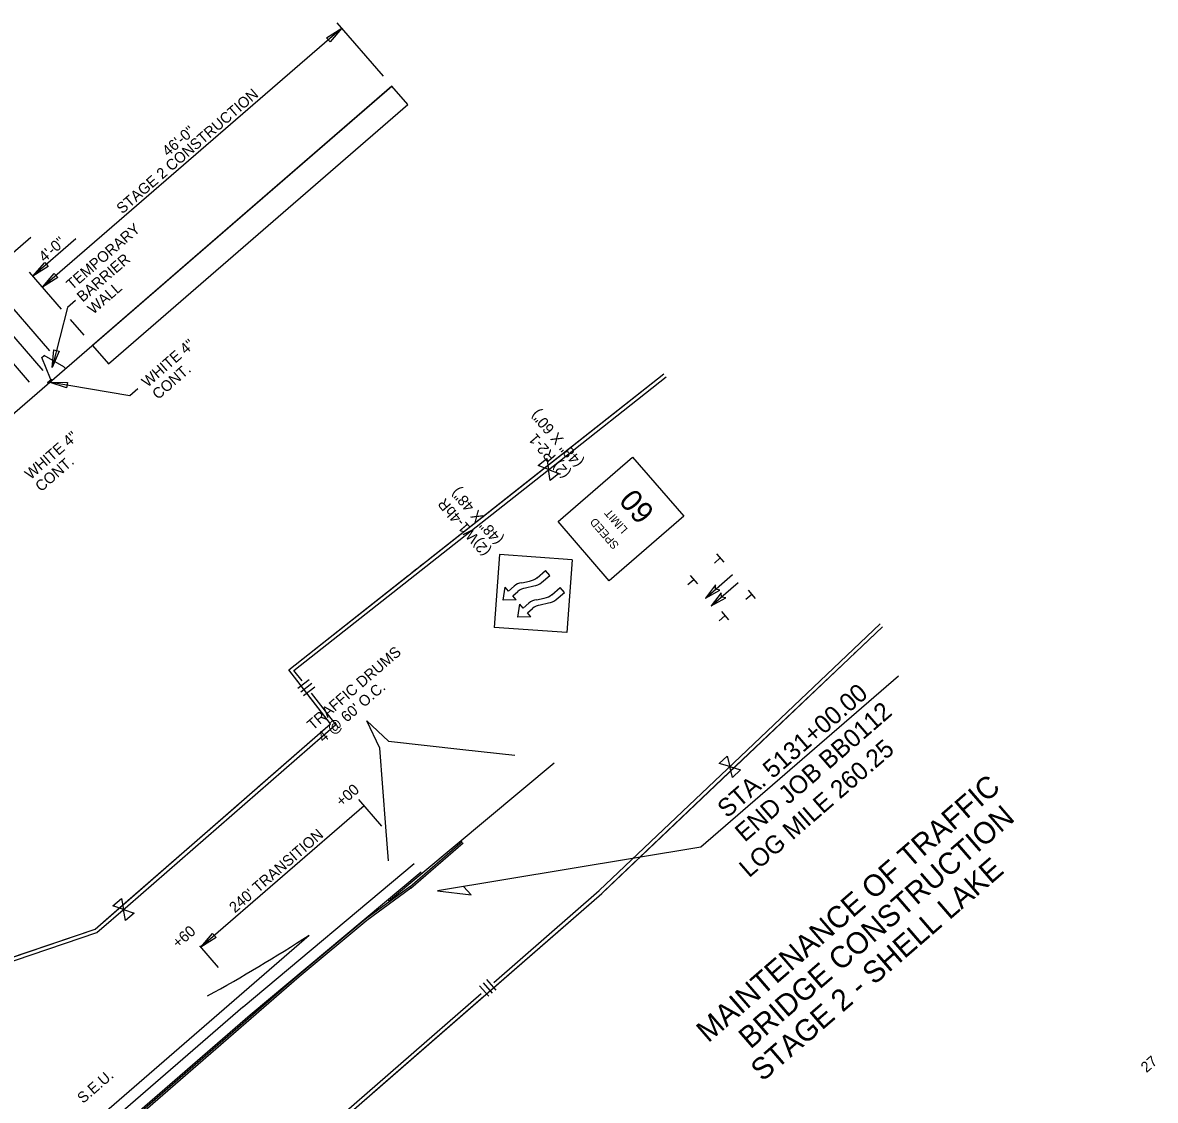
# Model space of a CAD drawing. Extents: x 259983 to 267998, y 211467 to 219827.
# Drawn here: x 263992 to 265251, y 216417 to 217614 of the extents above; entities that cross this region are included whole.
import ezdxf

# ---------------------------------------------------------------- set-up
doc = ezdxf.new("R2010")
doc.units = 0
for name, color, linetype in [('1', 7, 'Continuous'), ('Default', 7, 'Continuous'), ('Level 24', 7, 'Continuous'), ('Level 43', 7, 'Continuous'), ('Level 58', 7, 'Continuous'), ('Level 59', 7, 'Continuous'), ('Level 6', 7, 'Continuous'), ('R-W - CofA', 7, 'Continuous'), ('R_Border Notes', 7, 'Continuous'), ('R_MOT', 7, 'Continuous'), ('R_MOT STAGE 1', 7, 'Continuous'), ('R_MOT STAGE 2', 7, 'Continuous')]:
    doc.layers.add(name, color=color, linetype=linetype)

msp = doc.modelspace()

# ---------------------------------------------------------------- linework, layer by layer
at = {"layer": '1'}
for p, q in [((264346.9, 217608.3), (264014.1, 217320.3)), ((264393, 217554.9), (264341.6, 217614.3)), ((264420.4, 217523.3), (264402.6, 217543.9)), ((264001.1, 217375.6), (263951, 217332.2)), ((264051.4, 217373.9), (264003.6, 217332.5)), ((264022.4, 217249.7), (263946.2, 217337.7)), ((264035.3, 217295.9), (263999.7, 217337)), ((263999.9, 217214.6), (263924.5, 217301.7)), ((264015, 217227.7), (263961.8, 217289.1)), ((264060.4, 217267), (264045.3, 217284.4)), ((264111.1, 217199.5), (264021.7, 217214.7)), ((264120, 217207.2), (264111.1, 217199.5))]:
    msp.add_line(p, q, dxfattribs=at)
for points in [[(264329.9, 217597.6), (264346.9, 217608.3), (264333.8, 217593.1)], [(264020.5, 217343.2), (264003.6, 217332.5), (264016.6, 217347.8)], [(264031.1, 217331), (264014.1, 217320.3), (264027.1, 217335.6)], [(264032.7, 217249.3), (264024.9, 217230.9), (264026.9, 217250.8)], [(264040.8, 217208.4), (264021.7, 217214.7), (264041.8, 217214.4)], [(264207.2, 216597.6), (264190.2, 216586.9), (264203.2, 216602.1)]]:
    msp.add_lwpolyline(points, close=True, dxfattribs=at)
for points in [[(264050.9, 217305.4), (264042.1, 217297.7), (264024.9, 217230.9)], [(264395.7, 216720.6), (264389, 216808), (264374.6, 216838.5), (264398.8, 216815.8), (264481.3, 216806.7)], [(264481.3, 216806.7), (264539.3, 216800.3)], [(264398.6, 216683), (264395.7, 216720.6)]]:
    msp.add_lwpolyline(points, dxfattribs=at)
at = {"layer": 'Default'}
for p, q in [((264013.3, 217242.2), (264016, 217244.6)), ((264022.9, 217218.6), (264013.3, 217242.2)), ((264038, 217231.7), (264016, 217244.6)), ((264039.6, 217229.8), (264038, 217231.7)), ((264024.5, 217216.7), (264022.9, 217218.6))]:
    msp.add_line(p, q, dxfattribs=at)
msp.add_lwpolyline([(264019.8, 217214.3), (264023.7, 217217.7), (264024.5, 217216.7), (264020.7, 217213.3)], close=True, dxfattribs=at)
at = {"layer": 'Level 24'}
for points in [[(264965.4, 216888), (264745.8, 216697.9)], [(264745.8, 216697.9), (264453.1, 216649.6)]]:
    msp.add_lwpolyline(points, dxfattribs=at)
at = {"layer": 'Level 43'}
for points in [[(264750.9, 216974.9), (264780.9, 217000.9)], [(264757.4, 216966.2), (264787.5, 216992.2)]]:
    msp.add_lwpolyline(points, dxfattribs=at)
at = {"layer": 'Level 58'}
for points in [[(264762, 216989.5), (264750.9, 216974.9), (264766.9, 216983.8), (264762.2, 216984.7)], [(264768.6, 216980.8), (264757.4, 216966.2), (264773.5, 216975.1), (264768.8, 216976)]]:
    msp.add_lwpolyline(points, close=True, dxfattribs=at)
at = {"layer": 'Level 59'}
msp.add_lwpolyline([(264482.2, 216654.4), (264453.1, 216649.6), (264490.7, 216645.1)], close=True, dxfattribs=at)
at = {"layer": 'R-W - CofA'}
for p, q in [((264565.1, 217122.3), (264574.9, 217130)), ((264574.9, 217130), (264576.7, 217117.7)), ((264576.7, 217117.7), (264565.1, 217122.3)), ((264578.5, 217105.4), (264576.7, 217117.7)), ((264576.7, 217117.7), (264588.2, 217113.1)), ((264588.2, 217113.1), (264578.5, 217105.4)), ((264298, 216874.9), (264310.5, 216884.5)), ((264301.2, 216870.7), (264313.7, 216880.4)), ((264304.4, 216866.5), (264317, 216876.2)), ((264766.4, 216790.9), (264775.2, 216799.3)), ((264778.1, 216787.5), (264766.4, 216790.9)), ((264775.2, 216799.3), (264778.1, 216787.5)), ((264780.9, 216775.6), (264778.1, 216787.5)), ((264778.1, 216787.5), (264789.8, 216784)), ((264789.8, 216784), (264780.9, 216775.6)), ((264092.4, 216632.8), (264101.8, 216641)), ((264101.8, 216641), (264104.2, 216628.8)), ((264104.2, 216628.8), (264092.4, 216632.8)), ((264106.6, 216616.6), (264104.2, 216628.8)), ((264104.2, 216628.8), (264116, 216624.8)), ((264116, 216624.8), (264106.6, 216616.6)), ((264507.7, 216550.8), (264517.9, 216539.1)), ((264499.9, 216544), (264510.1, 216532.3)), ((264503.8, 216547.4), (264514, 216535.7))]:
    msp.add_line(p, q, dxfattribs=at)
for points in [[(263759.5, 216500.7), (264072.6, 216606.9), (264334.3, 216834.9), (264287.8, 216895.1), (264704.6, 217224)], [(264578.9, 217124.8), (264704.6, 217224)], [(264581.6, 217121.5), (264707.4, 217220.8)], [(264293.6, 216894.4), (264581.6, 217121.5)], [(264443.2, 217017.8), (264578.9, 217124.8)], [(264434, 217010.5), (264439, 217014.5)], [(264424.7, 217003.2), (264429.8, 217007.2)], [(264287.8, 216895.1), (264420.5, 216999.9)], [(264019.3, 215973.1), (264108, 216186.8), (264635.8, 216646.6), (264947.8, 216943)], [(264782.5, 216791.7), (264945.1, 216946.1)], [(264924.5, 216920.8), (264947.8, 216943)], [(264916.1, 216912.9), (264920.7, 216917.2)], [(264785.3, 216788.7), (264903.9, 216901.3)], [(264907.7, 216904.9), (264912.3, 216909.2)], [(264299.4, 216880.1), (264287.8, 216895.1)], [(264302.7, 216882.7), (264293.6, 216894.4)], [(264108.9, 216632.9), (264340.1, 216834.3), (264313.2, 216869.1)], [(264253.6, 216764.6), (264334.3, 216834.9), (264309.8, 216866.6)], [(264515.9, 216547.7), (264633, 216649.7), (264782.5, 216791.7)], [(264662.3, 216671.8), (264785.3, 216788.7)], [(264235.8, 216749.1), (264240.6, 216753.3)], [(264244.7, 216756.8), (264249.5, 216761)], [(264106.1, 216636.1), (264231.8, 216745.5)], [(264653.9, 216663.9), (264658.5, 216668.2)], [(264518.7, 216544.6), (264635.8, 216646.6), (264641.7, 216652.3)], [(264645.5, 216655.9), (264650.1, 216660.2)], [(263767.1, 216498.8), (264074.7, 216603.1), (264108.9, 216632.9)], [(263951, 216565.6), (264072.6, 216606.9), (264106.1, 216636.1)], [(264233.9, 216301.9), (264501.9, 216535.5)], [(264381.3, 216424.9), (264504.6, 216532.3)], [(264372.6, 216417.3), (264377.3, 216421.4)]]:
    msp.add_lwpolyline(points, dxfattribs=at)
at = {"layer": 'R_MOT'}
for p, q in [((264522, 217023.1), (264516.1, 216942.3)), ((264602.7, 217017.3), (264522, 217023.1)), ((264602.7, 217017.3), (264596.9, 216936.5)), ((264767.4, 217019.4), (264760.9, 217013.8)), ((264763.4, 217024), (264771.4, 217014.8)), ((264564.1, 216997.4), (264573.2, 217005.3)), ((264577.9, 216999.9), (264573.2, 217005.3)), ((264546.9, 216991.7), (264555.5, 216993.7)), ((264568.7, 216992.1), (264577.9, 216999.9)), ((264738, 216995.2), (264731.6, 216989.6)), ((264734, 216999.8), (264742.1, 216990.6)), ((264526.1, 216972.6), (264528.3, 216987.1)), ((264532.2, 216982.6), (264528.3, 216987.1)), ((264532.2, 216982.6), (264538.4, 216987.9)), ((264536.9, 216977.2), (264542.6, 216982.2)), ((264540.7, 216972.7), (264536.9, 216977.2)), ((264551.1, 216986.2), (264560.1, 216988.3)), ((264580.4, 216978.6), (264589.5, 216986.5)), ((264585.1, 216973.2), (264594.2, 216981.1)), ((264594.2, 216981.1), (264589.5, 216986.5)), ((264802.4, 216978.9), (264796, 216973.3)), ((264798.4, 216983.5), (264806.4, 216974.3)), ((264540.7, 216972.7), (264526.1, 216972.6)), ((264542.5, 216953.8), (264544.6, 216968.2)), ((264548.5, 216963.7), (264544.6, 216968.2)), ((264548.5, 216963.7), (264554.7, 216969.1)), ((264563.2, 216972.8), (264571.8, 216974.9)), ((264567.4, 216967.3), (264576.5, 216969.5)), ((264557.1, 216953.9), (264542.5, 216953.8)), ((264553.2, 216958.4), (264558.9, 216963.3)), ((264557.1, 216953.9), (264553.2, 216958.4)), ((264772.7, 216955.2), (264766.2, 216949.6)), ((264768.7, 216959.8), (264776.7, 216950.5)), ((264596.9, 216936.5), (264516.1, 216942.3))]:
    msp.add_line(p, q, dxfattribs=at)
msp.add_lwpolyline([(264587.2, 217059.8), (264670, 217131.4), (264726.9, 217065.7), (264644, 216994.1)], close=True, dxfattribs=at)
for centre, major_axis in [((264550.2, 216974.8), (-11.6, 13.4)), ((264552.1, 217010.7), (11.6, -13.4)), ((264556.9, 217005.2), (11.6, -13.4)), ((264554.5, 216969), (-11.6, 13.4)), ((264568.5, 216991.8), (11.6, -13.4)), ((264566.6, 216955.9), (-11.6, 13.4)), ((264570.8, 216950.2), (-11.6, 13.4)), ((264573.2, 216986.4), (11.6, -13.4))]:
    msp.add_ellipse(centre, major_axis=major_axis, ratio=0.9, start_param=5.717125, end_param=6.306311, dxfattribs=at)
at = {"layer": 'R_MOT STAGE 1'}
for p, q in [((264582.9, 216791.4), (264398.7, 216637.5)), ((264422.3, 216654), (264480.5, 216704.4)), ((264423.6, 216652.5), (264481.8, 216702.9)), ((264237.3, 216520.7), (264427.2, 216679.9)), ((264245, 216511.5), (264434.9, 216670.7)), ((264422.3, 216654), (264373.3, 216618.1)), ((264423.5, 216652.4), (264374.6, 216616.6)), ((264373.3, 216618.1), (264298.4, 216555.3)), ((264374.6, 216616.6), (264299.6, 216553.8)), ((263578.6, 215966.6), (264310.4, 216600.1)), ((264298.4, 216555.3), (263057.4, 215481)), ((264299.6, 216553.8), (263058.7, 215479.5)), ((263048.2, 215491.5), (264237, 216520.7)), ((263056, 215482.5), (264244.9, 216511.7))]:
    msp.add_line(p, q, dxfattribs=at)
msp.add_arc((263271.5, 218211.6), 1917.4, 298.8832, 302.8104, dxfattribs=at)
at = {"layer": 'R_MOT STAGE 2'}
for p, q in [((263767.4, 216994.1), (264402.6, 217543.9)), ((264391.3, 216721.3), (264365.7, 216750.9)), ((264371.7, 216744), (264190.2, 216586.9)), ((264209.8, 216564.2), (264189, 216588.3))]:
    msp.add_line(p, q, dxfattribs=at)
msp.add_lwpolyline([(264069.7, 217255.7), (264087.5, 217235.1), (264420.4, 217523.3), (264402.6, 217543.9)], close=True, dxfattribs=at)

# ---------------------------------------------------------------- texts
at = {"layer": '1'}
for s, rotation, p in [('TEMPORARY', 40.8833, (264047, 217316.7)), ('4\'-0"', 40.8733, (264016.4, 217347.6)), ('BARRIER', 40.8833, (264058.8, 217303.1)), ('WALL', 40.8833, (264070.6, 217289.5)), ('WHITE 4"', 40.8833, (264130.8, 217208.4)), ('CONT.', 40.8833, (264142.6, 217194.8)), ('WHITE 4"', 40.8833, (264000.9, 217105.9)), ('CONT.', 40.8833, (264012.6, 217092.3)), ('TRAFFIC DRUMS', 40.8745, (264314.7, 216827.4)), ("4 @ 60' O.C.", 40.8745, (264326.5, 216813.8)), ("240' TRANSITION", 40.8733, (264228, 216624.3)), ('S.E.U.', 40.8733, (264059.2, 216412.6))]:
    msp.add_text(s, height=12, rotation=rotation, dxfattribs=at).set_placement(p)
at = {"layer": 'Level 24'}
for s, p in [('STA. 5131+00.00', (264775.1, 216729.6)), ('END JOB BB0112', (264794.7, 216702.9)), ('LOG MILE 260.25', (264799.4, 216663.3))]:
    msp.add_text(s, height=20, rotation=40.8833, dxfattribs=at).set_placement(p)
at = {"layer": 'Level 6'}
for s, p in [('MAINTENANCE OF TRAFFIC', (264754.1, 216479.9)), ('BRIDGE CONSTRUCTION', (264801, 216472.9)), ('STAGE 2 - SHELL LAKE', (264814.4, 216436.8))]:
    msp.add_text(s, height=24, rotation=40.8733, dxfattribs=at).set_placement(p)
at = {"layer": 'R_Border Notes'}
msp.add_text('27', height=11.78, rotation=40.8833, dxfattribs=at).set_placement((265241.2, 216446.8))
at = {"layer": 'R_MOT'}
for s, height, rotation, p in [('(48" X 60")', 12.129, 130.8555, (264616, 217126.3)), ('(2) R2-1', 12.13, 130.8555, (264601.5, 217113.8)), ('(48" X 48")', 12, 130.8833, (264526.8, 217040.3)), ('60', 24.26, 130.8555, (264695.7, 217070.9)), ('(2)W1-4bR', 12, 130.8833, (264512.8, 217027.5)), ('LIMIT', 9.05, 130.8555, (264665.1, 217051.4)), ('SPEED', 9.05, 130.8555, (264655.5, 217033.9))]:
    msp.add_text(s, height=height, rotation=rotation, dxfattribs=at).set_placement(p)
at = {"layer": 'R_MOT STAGE 2'}
for s, rotation, p in [('STAGE 2 CONSTRUCTION', 40.8833, (264102.8, 217401.2)), ('46\'-0"', 40.8833, (264153.6, 217465)), ('+00', 40.8821, (264346.7, 216742.4)), ('+60', 40.8821, (264164.9, 216585.1))]:
    msp.add_text(s, height=12, rotation=rotation, dxfattribs=at).set_placement(p)

doc.saveas('drawing.dxf')
